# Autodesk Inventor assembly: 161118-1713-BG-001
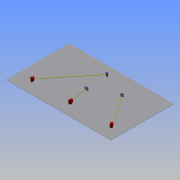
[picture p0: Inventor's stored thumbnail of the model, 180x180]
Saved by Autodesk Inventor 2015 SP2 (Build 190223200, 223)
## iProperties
Created: 2016-11
Part Number: 161118-1713-BG-001
Document SubType Name: Assembly
Designer: MP
Author: MP
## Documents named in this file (4)
- D:\DATA_IV\IV2015\CAD.de\Wanderkroete\161118-1713-BG-001.iam
- D:\DATA_IV\IV2015\CAD.de\Wanderkroete\161118-1713-BT-003.ipt
- D:\DATA_IV\IV2015\CAD.de\Wanderkroete\161118-1713-BT-001.ipt
- D:\DATA_IV\IV2015\CAD.de\Wanderkroete\161118-1713-BT-002.ipt
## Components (7 placed, 3 different names)
1. 161118-1713-BT-003:1 — Passend:1, Passend:2, Passend:3, Passend:4, Passend:5, Passend:6, Passend:7, Passend:8, Passend:9
2. 161118-1713-BT-001:1 — Passend:1, Passend:7, Fluchtend:1
3. 161118-1713-BT-001:2 — Passend:2, Passend:8, Fluchtend:2
4. 161118-1713-BT-001:3 — Passend:3, Passend:9, Fluchtend:3
5. 161118-1713-BT-002:1 — Passend:4, Fluchtend:1
6. 161118-1713-BT-002:2 — Passend:5, Fluchtend:2
7. 161118-1713-BT-002:3 — Passend:6, Fluchtend:3
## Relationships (12: Mate 9, Flush 3)
- Passend:1 [Mate]: 161118-1713-BT-003:1 ↔ 161118-1713-BT-001:1
- Passend:2 [Mate]: 161118-1713-BT-003:1 ↔ 161118-1713-BT-001:2
- Passend:3 [Mate]: 161118-1713-BT-003:1 ↔ 161118-1713-BT-001:3
- Passend:4 [Mate]: 161118-1713-BT-003:1 ↔ 161118-1713-BT-002:1
- Passend:5 [Mate]: 161118-1713-BT-003:1 ↔ 161118-1713-BT-002:2
- Passend:6 [Mate]: 161118-1713-BT-003:1 ↔ 161118-1713-BT-002:3
- Passend:7 [Mate]: 161118-1713-BT-003:1 ↔ 161118-1713-BT-001:1
- Passend:8 [Mate]: 161118-1713-BT-003:1 ↔ 161118-1713-BT-001:2
- Passend:9 [Mate]: 161118-1713-BT-003:1 ↔ 161118-1713-BT-001:3
- Fluchtend:1 [Flush]: 161118-1713-BT-001:1 ↔ 161118-1713-BT-002:1
- Fluchtend:2 [Flush]: 161118-1713-BT-001:2 ↔ 161118-1713-BT-002:2
- Fluchtend:3 [Flush]: 161118-1713-BT-001:3 ↔ 161118-1713-BT-002:3
